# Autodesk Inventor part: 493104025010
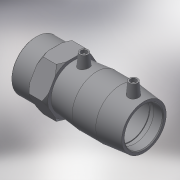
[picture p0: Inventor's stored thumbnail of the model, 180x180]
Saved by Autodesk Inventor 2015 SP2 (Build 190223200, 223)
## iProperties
Created: 2017-06
Part Number: 493104025010
Material: Generic
Description: PLASSON FEMALE TRANSITION COUPLER 25-1"
Document SubType Name: Modeling
Designer: KIM
Mass: 59.5002 g
Surface Area: 256.406 cm^2
Volume: 59.5002 cm^3
Density: 1 g/cm^3
Appearance: Default
Author: KIM
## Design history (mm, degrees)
derived "493104.ipt"
feature "Solid1::493104.ipt"
tag "TaggingFeature1"
body "Solid1"
other parameters: "d1" = 25, "d2" = 36, "d3" = 34, "d4" = 26.66667, "d5" = 32.4, "d6" = 23.75, "d7" = 25, "d8" = 168 deg, "d10" = 13.6, "d11" = 4.53333, "d29" = 42, "d30" = 14, "d31" = 28, "d34" = 5 deg, "d41" = 4, "d42" = 14, "d43" = 0, "d48" = 3, "d49" = 0, "d55" = 28, "d57" = 23, "d59" = 30.291, "d60" = 25.2, "d70" = 36, "d71" = 14, "d72" = 0, "d73" = 45 deg, "d74" = 2.3, "d75" = 45 deg, "d77" = 0.375, "d80" = 0.5, "d_" = 25, "L_" = 108, "L_1" = 34, "D_1" = 36, "A_" = 42, "d_2" = 12, "L_2" = 28, "D_" = 23, "R_p" = 30.291
